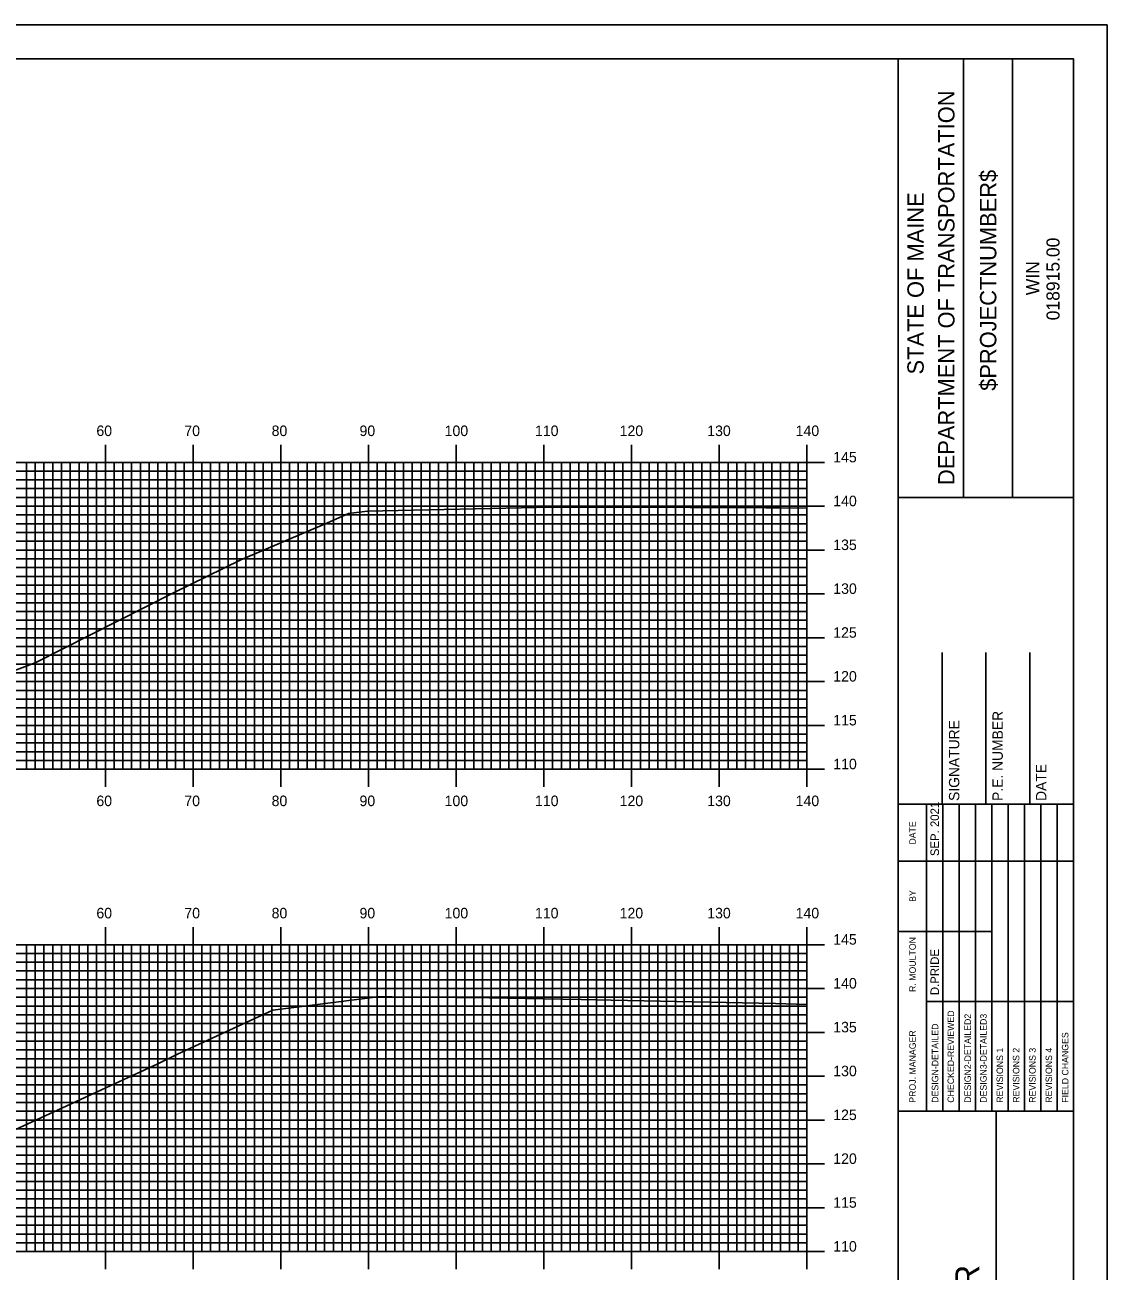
# Model space of a CAD drawing. Extents: x 853328 to 853671, y 364661 to 364881.
# Drawn here: x 853544.1 to 853667.5, y 364739.1 to 364881.3 of the extents above; entities that cross this region are included whole.
import ezdxf

# ---------------------------------------------------------------- set-up
doc = ezdxf.new("R2010")
doc.units = 0
for name, color, linetype in [('BORDER', 7, 'Continuous'), ('H_V ANNOTATION', 7, 'Continuous'), ('MAJOR', 7, 'Continuous'), ('MINOR', 7, 'Continuous'), ('PLOT BOUNDARY', 7, 'Continuous'), ('S_Roadway_Centerline', 7, 'Continuous')]:
    doc.layers.add(name, color=color, linetype=linetype)

msp = doc.modelspace()

# ---------------------------------------------------------------- linework, layer by layer
at = {"layer": 'BORDER'}
for p, q in [((853643.69, 364667.37), (853643.69, 364877.37)), ((853651.15, 364827.36), (853651.15, 364877.36)), ((853656.74, 364827.36), (853656.74, 364877.36)), ((853643.7, 364827.36), (853663.69, 364827.36)), ((853648.69, 364792.38), (853648.69, 364809.67)), ((853653.69, 364792.38), (853653.69, 364809.67)), ((853658.69, 364792.38), (853658.69, 364809.67)), ((853643.69, 364792.38), (853663.69, 364792.38)), ((853643.69, 364757.38), (853663.69, 364757.38)), ((853654.88, 364687.38), (853654.88, 364757.38))]:
    msp.add_line(p, q, dxfattribs=at)
msp.add_lwpolyline([(853343.69, 364667.37), (853663.69, 364667.37), (853663.69, 364877.37), (853343.69, 364877.37)], close=True, dxfattribs=at)
for points in [[(853646.92, 364785.88), (853646.92, 364792.38)], [(853648.79, 364757.38), (853648.79, 364792.38)], [(853650.65, 364792.38), (853650.65, 364757.38)], [(853652.52, 364757.38), (853652.52, 364792.38)], [(853654.38, 364757.38), (853654.38, 364792.38)], [(853656.24, 364757.38), (853656.24, 364792.38)], [(853658.11, 364757.38), (853658.11, 364792.38)], [(853659.97, 364757.38), (853659.97, 364792.38)], [(853661.83, 364757.38), (853661.83, 364792.38)], [(853646.93, 364757.38), (853646.93, 364790.96)], [(853643.69, 364785.88), (853663.69, 364785.88)], [(853643.69, 364777.88), (853646.93, 364777.88)], [(853646.92, 364777.88), (853654.38, 364777.88)], [(853646.92, 364769.88), (853663.69, 364769.88)]]:
    msp.add_lwpolyline(points, dxfattribs=at)
at = {"layer": 'MAJOR'}
for p, q in [((853553.29, 364833.38), (853553.29, 364831.37)), ((853563.29, 364833.38), (853563.29, 364831.37)), ((853573.29, 364833.38), (853573.29, 364831.37)), ((853583.29, 364833.38), (853583.29, 364831.37)), ((853593.29, 364833.38), (853593.29, 364831.37)), ((853603.29, 364833.38), (853603.29, 364831.37)), ((853613.29, 364833.38), (853613.29, 364831.37)), ((853623.29, 364833.38), (853623.29, 364831.37)), ((853633.29, 364833.38), (853633.29, 364831.37)), ((853353.29, 364831.37), (853633.29, 364831.37)), ((853353.29, 364831.37), (853633.29, 364831.37)), ((853553.29, 364796.37), (853553.29, 364831.37)), ((853563.29, 364796.37), (853563.29, 364831.37)), ((853573.29, 364796.37), (853573.29, 364831.37)), ((853583.29, 364796.37), (853583.29, 364831.37)), ((853593.29, 364796.37), (853593.29, 364831.37)), ((853603.29, 364796.37), (853603.29, 364831.37)), ((853613.29, 364796.37), (853613.29, 364831.37)), ((853623.29, 364796.37), (853623.29, 364831.37)), ((853635.3, 364831.37), (853631.29, 364831.37)), ((853633.29, 364796.37), (853633.29, 364831.37)), ((853633.29, 364796.37), (853633.29, 364831.37)), ((853353.29, 364826.37), (853633.29, 364826.37)), ((853635.3, 364826.37), (853631.29, 364826.37)), ((853353.29, 364821.37), (853633.29, 364821.37)), ((853635.3, 364821.37), (853631.29, 364821.37)), ((853353.29, 364816.37), (853633.29, 364816.37)), ((853635.3, 364816.37), (853631.29, 364816.37)), ((853353.29, 364811.37), (853633.29, 364811.37)), ((853635.3, 364811.37), (853631.29, 364811.37)), ((853353.29, 364806.37), (853633.29, 364806.37)), ((853635.3, 364806.37), (853631.29, 364806.37)), ((853353.29, 364801.37), (853633.29, 364801.37)), ((853635.3, 364801.37), (853631.29, 364801.37)), ((853353.29, 364796.37), (853633.29, 364796.37)), ((853353.29, 364796.37), (853633.29, 364796.37)), ((853553.29, 364794.37), (853553.29, 364796.37)), ((853563.29, 364794.37), (853563.29, 364796.37)), ((853573.29, 364794.37), (853573.29, 364796.37)), ((853583.29, 364794.37), (853583.29, 364796.37)), ((853593.29, 364794.37), (853593.29, 364796.37)), ((853603.29, 364794.37), (853603.29, 364796.37)), ((853613.29, 364794.37), (853613.29, 364796.37)), ((853623.29, 364794.37), (853623.29, 364796.37)), ((853635.3, 364796.37), (853631.29, 364796.37)), ((853633.29, 364794.37), (853633.29, 364796.37)), ((853553.29, 364778.38), (853553.29, 364776.37)), ((853563.29, 364778.38), (853563.29, 364776.37)), ((853573.29, 364778.38), (853573.29, 364776.37)), ((853583.29, 364778.38), (853583.29, 364776.37)), ((853593.29, 364778.38), (853593.29, 364776.37)), ((853603.29, 364778.38), (853603.29, 364776.37)), ((853613.29, 364778.38), (853613.29, 364776.37)), ((853623.29, 364778.38), (853623.29, 364776.37)), ((853633.29, 364778.38), (853633.29, 364776.37)), ((853353.29, 364776.37), (853633.29, 364776.37)), ((853353.29, 364776.37), (853633.29, 364776.37)), ((853553.29, 364741.37), (853553.29, 364776.37)), ((853563.29, 364741.37), (853563.29, 364776.37)), ((853573.29, 364741.37), (853573.29, 364776.37)), ((853583.29, 364741.37), (853583.29, 364776.37)), ((853593.29, 364741.37), (853593.29, 364776.37)), ((853603.29, 364741.37), (853603.29, 364776.37)), ((853613.29, 364741.37), (853613.29, 364776.37)), ((853623.29, 364741.37), (853623.29, 364776.37)), ((853635.3, 364776.37), (853631.29, 364776.37)), ((853633.29, 364741.37), (853633.29, 364776.37)), ((853633.29, 364741.37), (853633.29, 364776.37)), ((853353.29, 364771.37), (853633.29, 364771.37)), ((853635.3, 364771.37), (853631.29, 364771.37)), ((853353.29, 364766.37), (853633.29, 364766.37)), ((853635.3, 364766.37), (853631.29, 364766.37)), ((853353.29, 364761.37), (853633.29, 364761.37)), ((853635.3, 364761.37), (853631.29, 364761.37)), ((853353.29, 364756.37), (853633.29, 364756.37)), ((853635.3, 364756.37), (853631.29, 364756.37)), ((853353.29, 364751.37), (853633.29, 364751.37)), ((853635.3, 364751.37), (853631.29, 364751.37)), ((853353.29, 364746.37), (853633.29, 364746.37)), ((853635.3, 364746.37), (853631.29, 364746.37)), ((853353.29, 364741.37), (853633.29, 364741.37)), ((853353.29, 364741.37), (853633.29, 364741.37)), ((853553.29, 364739.37), (853553.29, 364741.37)), ((853563.29, 364739.37), (853563.29, 364741.37)), ((853573.29, 364739.37), (853573.29, 364741.37)), ((853583.29, 364739.37), (853583.29, 364741.37)), ((853593.29, 364739.37), (853593.29, 364741.37)), ((853603.29, 364739.37), (853603.29, 364741.37)), ((853613.29, 364739.37), (853613.29, 364741.37)), ((853623.29, 364739.37), (853623.29, 364741.37)), ((853635.3, 364741.37), (853631.29, 364741.37)), ((853633.29, 364739.37), (853633.29, 364741.37))]:
    msp.add_line(p, q, dxfattribs=at)
at = {"layer": 'MINOR'}
for p, q in [((853544.29, 364796.37), (853544.29, 364831.37)), ((853545.29, 364796.37), (853545.29, 364831.37)), ((853546.29, 364796.37), (853546.29, 364831.37)), ((853547.29, 364796.37), (853547.29, 364831.37)), ((853548.29, 364796.37), (853548.29, 364831.37)), ((853549.29, 364796.37), (853549.29, 364831.37)), ((853550.29, 364796.37), (853550.29, 364831.37)), ((853551.29, 364796.37), (853551.29, 364831.37)), ((853552.29, 364796.37), (853552.29, 364831.37)), ((853554.29, 364796.37), (853554.29, 364831.37)), ((853555.29, 364796.37), (853555.29, 364831.37)), ((853556.29, 364796.37), (853556.29, 364831.37)), ((853557.29, 364796.37), (853557.29, 364831.37)), ((853558.29, 364796.37), (853558.29, 364831.37)), ((853559.29, 364796.37), (853559.29, 364831.37)), ((853560.29, 364796.37), (853560.29, 364831.37)), ((853561.29, 364796.37), (853561.29, 364831.37)), ((853562.29, 364796.37), (853562.29, 364831.37)), ((853564.29, 364796.37), (853564.29, 364831.37)), ((853565.29, 364796.37), (853565.29, 364831.37)), ((853566.29, 364796.37), (853566.29, 364831.37)), ((853567.29, 364796.37), (853567.29, 364831.37)), ((853568.29, 364796.37), (853568.29, 364831.37)), ((853569.29, 364796.37), (853569.29, 364831.37)), ((853570.29, 364796.37), (853570.29, 364831.37)), ((853571.29, 364796.37), (853571.29, 364831.37)), ((853572.29, 364796.37), (853572.29, 364831.37)), ((853574.29, 364796.37), (853574.29, 364831.37)), ((853575.29, 364796.37), (853575.29, 364831.37)), ((853576.29, 364796.37), (853576.29, 364831.37)), ((853577.29, 364796.37), (853577.29, 364831.37)), ((853578.29, 364796.37), (853578.29, 364831.37)), ((853579.29, 364796.37), (853579.29, 364831.37)), ((853580.29, 364796.37), (853580.29, 364831.37)), ((853581.29, 364796.37), (853581.29, 364831.37)), ((853582.29, 364796.37), (853582.29, 364831.37)), ((853584.29, 364796.37), (853584.29, 364831.37)), ((853585.29, 364796.37), (853585.29, 364831.37)), ((853586.29, 364796.37), (853586.29, 364831.37)), ((853587.29, 364796.37), (853587.29, 364831.37)), ((853588.29, 364796.37), (853588.29, 364831.37)), ((853589.29, 364796.37), (853589.29, 364831.37)), ((853590.29, 364796.37), (853590.29, 364831.37)), ((853591.29, 364796.37), (853591.29, 364831.37)), ((853592.29, 364796.37), (853592.29, 364831.37)), ((853594.29, 364796.37), (853594.29, 364831.37)), ((853595.29, 364796.37), (853595.29, 364831.37)), ((853596.29, 364796.37), (853596.29, 364831.37)), ((853597.29, 364796.37), (853597.29, 364831.37)), ((853598.29, 364796.37), (853598.29, 364831.37)), ((853599.29, 364796.37), (853599.29, 364831.37)), ((853600.29, 364796.37), (853600.29, 364831.37)), ((853601.29, 364796.37), (853601.29, 364831.37)), ((853602.29, 364796.37), (853602.29, 364831.37)), ((853604.29, 364796.37), (853604.29, 364831.37)), ((853605.29, 364796.37), (853605.29, 364831.37)), ((853606.29, 364796.37), (853606.29, 364831.37)), ((853607.29, 364796.37), (853607.29, 364831.37)), ((853608.29, 364796.37), (853608.29, 364831.37)), ((853609.29, 364796.37), (853609.29, 364831.37)), ((853610.29, 364796.37), (853610.29, 364831.37)), ((853611.29, 364796.37), (853611.29, 364831.37)), ((853612.29, 364796.37), (853612.29, 364831.37)), ((853614.29, 364796.37), (853614.29, 364831.37)), ((853615.29, 364796.37), (853615.29, 364831.37)), ((853616.29, 364796.37), (853616.29, 364831.37)), ((853617.29, 364796.37), (853617.29, 364831.37)), ((853618.29, 364796.37), (853618.29, 364831.37)), ((853619.29, 364796.37), (853619.29, 364831.37)), ((853620.29, 364796.37), (853620.29, 364831.37)), ((853621.29, 364796.37), (853621.29, 364831.37)), ((853622.29, 364796.37), (853622.29, 364831.37)), ((853624.29, 364796.37), (853624.29, 364831.37)), ((853625.29, 364796.37), (853625.29, 364831.37)), ((853626.29, 364796.37), (853626.29, 364831.37)), ((853627.29, 364796.37), (853627.29, 364831.37)), ((853628.29, 364796.37), (853628.29, 364831.37)), ((853629.29, 364796.37), (853629.29, 364831.37)), ((853630.29, 364796.37), (853630.29, 364831.37)), ((853631.29, 364796.37), (853631.29, 364831.37)), ((853632.29, 364796.37), (853632.29, 364831.37)), ((853353.29, 364830.37), (853633.29, 364830.37)), ((853633.29, 364830.37), (853631.29, 364830.37)), ((853353.29, 364829.37), (853633.29, 364829.37)), ((853353.29, 364828.37), (853633.29, 364828.37)), ((853633.29, 364829.37), (853631.29, 364829.37)), ((853633.29, 364828.37), (853631.29, 364828.37)), ((853353.29, 364827.37), (853633.29, 364827.37)), ((853633.29, 364827.37), (853631.29, 364827.37)), ((853353.29, 364825.37), (853633.29, 364825.37)), ((853353.29, 364824.37), (853633.29, 364824.37)), ((853633.29, 364825.37), (853631.29, 364825.37)), ((853633.29, 364824.37), (853631.29, 364824.37)), ((853353.29, 364823.37), (853633.29, 364823.37)), ((853633.29, 364823.37), (853631.29, 364823.37)), ((853353.29, 364822.37), (853633.29, 364822.37)), ((853633.29, 364822.37), (853631.29, 364822.37)), ((853353.29, 364820.37), (853633.29, 364820.37)), ((853633.29, 364820.37), (853631.29, 364820.37)), ((853353.29, 364819.37), (853633.29, 364819.37)), ((853633.29, 364819.37), (853631.29, 364819.37)), ((853353.29, 364818.37), (853633.29, 364818.37)), ((853353.29, 364817.37), (853633.29, 364817.37)), ((853633.29, 364818.37), (853631.29, 364818.37)), ((853633.29, 364817.37), (853631.29, 364817.37)), ((853353.29, 364815.37), (853633.29, 364815.37)), ((853353.29, 364814.37), (853633.29, 364814.37)), ((853633.29, 364815.37), (853631.29, 364815.37)), ((853633.29, 364814.37), (853631.29, 364814.37)), ((853353.29, 364813.37), (853633.29, 364813.37)), ((853633.29, 364813.37), (853631.29, 364813.37)), ((853353.29, 364812.37), (853633.29, 364812.37)), ((853633.29, 364812.37), (853631.29, 364812.37)), ((853353.29, 364810.37), (853633.29, 364810.37)), ((853633.29, 364810.37), (853631.29, 364810.37)), ((853353.29, 364809.37), (853633.29, 364809.37)), ((853633.29, 364809.37), (853631.29, 364809.37)), ((853353.29, 364808.37), (853633.29, 364808.37)), ((853353.29, 364807.37), (853633.29, 364807.37)), ((853633.29, 364808.37), (853631.29, 364808.37)), ((853633.29, 364807.37), (853631.29, 364807.37)), ((853353.29, 364805.37), (853633.29, 364805.37)), ((853353.29, 364804.37), (853633.29, 364804.37)), ((853633.29, 364805.37), (853631.29, 364805.37)), ((853633.29, 364804.37), (853631.29, 364804.37)), ((853353.29, 364803.37), (853633.29, 364803.37)), ((853633.29, 364803.37), (853631.29, 364803.37)), ((853353.29, 364802.37), (853633.29, 364802.37)), ((853633.29, 364802.37), (853631.29, 364802.37)), ((853353.29, 364800.37), (853633.29, 364800.37)), ((853633.29, 364800.37), (853631.29, 364800.37)), ((853353.29, 364799.37), (853633.29, 364799.37)), ((853633.29, 364799.37), (853631.29, 364799.37)), ((853353.29, 364798.37), (853633.29, 364798.37)), ((853353.29, 364797.37), (853633.29, 364797.37)), ((853633.29, 364798.37), (853631.29, 364798.37)), ((853633.29, 364797.37), (853631.29, 364797.37)), ((853544.29, 364741.37), (853544.29, 364776.37)), ((853545.29, 364741.37), (853545.29, 364776.37)), ((853546.29, 364741.37), (853546.29, 364776.37)), ((853547.29, 364741.37), (853547.29, 364776.37)), ((853548.29, 364741.37), (853548.29, 364776.37)), ((853549.29, 364741.37), (853549.29, 364776.37)), ((853550.29, 364741.37), (853550.29, 364776.37)), ((853551.29, 364741.37), (853551.29, 364776.37)), ((853552.29, 364741.37), (853552.29, 364776.37)), ((853554.29, 364741.37), (853554.29, 364776.37)), ((853555.29, 364741.37), (853555.29, 364776.37)), ((853556.29, 364741.37), (853556.29, 364776.37)), ((853557.29, 364741.37), (853557.29, 364776.37)), ((853558.29, 364741.37), (853558.29, 364776.37)), ((853559.29, 364741.37), (853559.29, 364776.37)), ((853560.29, 364741.37), (853560.29, 364776.37)), ((853561.29, 364741.37), (853561.29, 364776.37)), ((853562.29, 364741.37), (853562.29, 364776.37)), ((853564.29, 364741.37), (853564.29, 364776.37)), ((853565.29, 364741.37), (853565.29, 364776.37)), ((853566.29, 364741.37), (853566.29, 364776.37)), ((853567.29, 364741.37), (853567.29, 364776.37)), ((853568.29, 364741.37), (853568.29, 364776.37)), ((853569.29, 364741.37), (853569.29, 364776.37)), ((853570.29, 364741.37), (853570.29, 364776.37)), ((853571.29, 364741.37), (853571.29, 364776.37)), ((853572.29, 364741.37), (853572.29, 364776.37)), ((853574.29, 364741.37), (853574.29, 364776.37)), ((853575.29, 364741.37), (853575.29, 364776.37)), ((853576.29, 364741.37), (853576.29, 364776.37)), ((853577.29, 364741.37), (853577.29, 364776.37)), ((853578.29, 364741.37), (853578.29, 364776.37)), ((853579.29, 364741.37), (853579.29, 364776.37)), ((853580.29, 364741.37), (853580.29, 364776.37)), ((853581.29, 364741.37), (853581.29, 364776.37)), ((853582.29, 364741.37), (853582.29, 364776.37)), ((853584.29, 364741.37), (853584.29, 364776.37)), ((853585.29, 364741.37), (853585.29, 364776.37)), ((853586.29, 364741.37), (853586.29, 364776.37)), ((853587.29, 364741.37), (853587.29, 364776.37)), ((853588.29, 364741.37), (853588.29, 364776.37)), ((853589.29, 364741.37), (853589.29, 364776.37)), ((853590.29, 364741.37), (853590.29, 364776.37)), ((853591.29, 364741.37), (853591.29, 364776.37)), ((853592.29, 364741.37), (853592.29, 364776.37)), ((853594.29, 364741.37), (853594.29, 364776.37)), ((853595.29, 364741.37), (853595.29, 364776.37)), ((853596.29, 364741.37), (853596.29, 364776.37)), ((853597.29, 364741.37), (853597.29, 364776.37)), ((853598.29, 364741.37), (853598.29, 364776.37)), ((853599.29, 364741.37), (853599.29, 364776.37)), ((853600.29, 364741.37), (853600.29, 364776.37)), ((853601.29, 364741.37), (853601.29, 364776.37)), ((853602.29, 364741.37), (853602.29, 364776.37)), ((853604.29, 364741.37), (853604.29, 364776.37)), ((853605.29, 364741.37), (853605.29, 364776.37)), ((853606.29, 364741.37), (853606.29, 364776.37)), ((853607.29, 364741.37), (853607.29, 364776.37)), ((853608.29, 364741.37), (853608.29, 364776.37)), ((853609.29, 364741.37), (853609.29, 364776.37)), ((853610.29, 364741.37), (853610.29, 364776.37)), ((853611.29, 364741.37), (853611.29, 364776.37)), ((853612.29, 364741.37), (853612.29, 364776.37)), ((853614.29, 364741.37), (853614.29, 364776.37)), ((853615.29, 364741.37), (853615.29, 364776.37)), ((853616.29, 364741.37), (853616.29, 364776.37)), ((853617.29, 364741.37), (853617.29, 364776.37)), ((853618.29, 364741.37), (853618.29, 364776.37)), ((853619.29, 364741.37), (853619.29, 364776.37)), ((853620.29, 364741.37), (853620.29, 364776.37)), ((853621.29, 364741.37), (853621.29, 364776.37)), ((853622.29, 364741.37), (853622.29, 364776.37)), ((853624.29, 364741.37), (853624.29, 364776.37)), ((853625.29, 364741.37), (853625.29, 364776.37)), ((853626.29, 364741.37), (853626.29, 364776.37)), ((853627.29, 364741.37), (853627.29, 364776.37)), ((853628.29, 364741.37), (853628.29, 364776.37)), ((853629.29, 364741.37), (853629.29, 364776.37)), ((853630.29, 364741.37), (853630.29, 364776.37)), ((853631.29, 364741.37), (853631.29, 364776.37)), ((853632.29, 364741.37), (853632.29, 364776.37)), ((853353.29, 364775.37), (853633.29, 364775.37)), ((853353.29, 364774.37), (853633.29, 364774.37)), ((853633.29, 364775.37), (853631.29, 364775.37)), ((853633.29, 364774.37), (853631.29, 364774.37)), ((853353.29, 364773.37), (853633.29, 364773.37)), ((853633.29, 364773.37), (853631.29, 364773.37)), ((853353.29, 364772.37), (853633.29, 364772.37)), ((853633.29, 364772.37), (853631.29, 364772.37)), ((853353.29, 364770.37), (853633.29, 364770.37)), ((853633.29, 364770.37), (853631.29, 364770.37)), ((853353.29, 364769.37), (853633.29, 364769.37)), ((853633.29, 364769.37), (853631.29, 364769.37)), ((853353.29, 364768.37), (853633.29, 364768.37)), ((853353.29, 364767.37), (853633.29, 364767.37)), ((853633.29, 364768.37), (853631.29, 364768.37)), ((853633.29, 364767.37), (853631.29, 364767.37)), ((853353.29, 364765.37), (853633.29, 364765.37)), ((853633.29, 364765.37), (853631.29, 364765.37)), ((853353.29, 364764.37), (853633.29, 364764.37)), ((853353.29, 364763.37), (853633.29, 364763.37)), ((853633.29, 364764.37), (853631.29, 364764.37)), ((853633.29, 364763.37), (853631.29, 364763.37)), ((853353.29, 364762.37), (853633.29, 364762.37)), ((853633.29, 364762.37), (853631.29, 364762.37)), ((853353.29, 364760.37), (853633.29, 364760.37)), ((853633.29, 364760.37), (853631.29, 364760.37)), ((853353.29, 364759.37), (853633.29, 364759.37)), ((853633.29, 364759.37), (853631.29, 364759.37)), ((853353.29, 364758.37), (853633.29, 364758.37)), ((853353.29, 364757.37), (853633.29, 364757.37)), ((853633.29, 364758.37), (853631.29, 364758.37)), ((853633.29, 364757.37), (853631.29, 364757.37)), ((853353.29, 364755.37), (853633.29, 364755.37)), ((853633.29, 364755.37), (853631.29, 364755.37)), ((853353.29, 364754.37), (853633.29, 364754.37)), ((853353.29, 364753.37), (853633.29, 364753.37)), ((853633.29, 364754.37), (853631.29, 364754.37)), ((853633.29, 364753.37), (853631.29, 364753.37)), ((853353.29, 364752.37), (853633.29, 364752.37)), ((853633.29, 364752.37), (853631.29, 364752.37)), ((853353.29, 364750.37), (853633.29, 364750.37)), ((853633.29, 364750.37), (853631.29, 364750.37)), ((853353.29, 364749.37), (853633.29, 364749.37)), ((853633.29, 364749.37), (853631.29, 364749.37)), ((853353.29, 364748.37), (853633.29, 364748.37)), ((853353.29, 364747.37), (853633.29, 364747.37)), ((853633.29, 364748.37), (853631.29, 364748.37)), ((853633.29, 364747.37), (853631.29, 364747.37)), ((853353.29, 364745.37), (853633.29, 364745.37)), ((853633.29, 364745.37), (853631.29, 364745.37)), ((853353.29, 364744.37), (853633.29, 364744.37)), ((853353.29, 364743.37), (853633.29, 364743.37)), ((853633.29, 364744.37), (853631.29, 364744.37)), ((853633.29, 364743.37), (853631.29, 364743.37)), ((853353.29, 364742.37), (853633.29, 364742.37)), ((853633.29, 364742.37), (853631.29, 364742.37))]:
    msp.add_line(p, q, dxfattribs=at)
at = {"layer": 'PLOT BOUNDARY'}
msp.add_lwpolyline([(853327.51, 364661.25), (853667.51, 364661.25), (853667.51, 364881.25), (853327.51, 364881.25)], close=True, dxfattribs=at)
at = {"layer": 'S_Roadway_Centerline'}
for points in [[(853539.28, 364806.27), (853545.28, 364808.52), (853561.07, 364816.51), (853568.75, 364820.24), (853578.56, 364824.44), (853581.03, 364825.54), (853583.18, 364825.79), (853604.21, 364826.26), (853604.82, 364826.26), (853605.4, 364826.27), (853611.36, 364826.25), (853628.61, 364826.19), (853630.34, 364826.17), (853633.29, 364826.14)], [(853539.98, 364753.87), (853559.29, 364762.8), (853561.53, 364763.88), (853572.4, 364768.92), (853584.36, 364770.44), (853585.99, 364770.43), (853597.04, 364770.3), (853607.54, 364770.13), (853610.95, 364770.05), (853629.72, 364769.67), (853633.29, 364769.56)]]:
    msp.add_lwpolyline(points, dxfattribs=at)

# ---------------------------------------------------------------- texts
at = {"layer": 'BORDER'}
for s, height, p in [('DEPARTMENT OF TRANSPORTATION', 1.8635, (853650.11, 364828.78)), ('$PROJECTNUMBER$', 1.8635, (853654.88, 364839.53)), ('STATE OF MAINE', 1.8635, (853646.6, 364841.39)), ('018915.00', 1.491, (853662.09, 364847.57)), ('WIN', 1.491, (853659.77, 364850.43)), ('P.E. NUMBER', 1.1811, (853655.62, 364792.76)), ('SIGNATURE', 1.181, (853650.66, 364792.76)), ('DATE', 1.181, (853660.58, 364792.76)), ('SEP. 2021', 0.969, (853648.34, 364786.47)), ('DATE', 0.743, (853645.7, 364787.79)), ('BY', 0.743, (853645.7, 364781.25)), ('R. MOULTON', 0.745, (853645.7, 364770.98)), ('D.PRIDE', 0.969, (853648.34, 364770.62)), ('CHECKED-REVIEWED', 0.7455, (853650.06, 364758.35)), ('DESIGN-DETAILED', 0.7455, (853648.27, 364758.35)), ('DESIGN2-DETAILED2', 0.7455, (853651.99, 364758.35)), ('DESIGN3-DETAILED3', 0.7455, (853653.78, 364758.35)), ('PROJ. MANAGER', 0.7455, (853645.7, 364758.35)), ('FIELD CHANGES', 0.7455, (853663.1, 364758.35)), ('REVISIONS 1', 0.7455, (853655.65, 364758.35)), ('REVISIONS 2', 0.7455, (853657.51, 364758.35)), ('REVISIONS 3', 0.7455, (853659.37, 364758.35)), ('REVISIONS 4', 0.7455, (853661.24, 364758.35)), ('I-395/ROUTE 9 CONNECTOR', 2.7557, (853652.96, 364689.7))]:
    msp.add_text(s, height=height, rotation=90, dxfattribs=at).set_placement(p)
at = {"layer": 'H_V ANNOTATION'}
for s, p in [('60', (853552.27, 364834.37)), ('70', (853562.3, 364834.37)), ('80', (853572.25, 364834.37)), ('90', (853582.27, 364834.37)), ('100', (853591.98, 364834.37)), ('110', (853602.28, 364834.37)), ('120', (853611.93, 364834.37)), ('130', (853621.92, 364834.37)), ('140', (853632, 364834.37)), ('145', (853636.29, 364831.37)), ('140', (853636.29, 364826.37)), ('135', (853636.29, 364821.37)), ('130', (853636.29, 364816.37)), ('125', (853636.29, 364811.37)), ('120', (853636.29, 364806.37)), ('115', (853636.29, 364801.37)), ('110', (853636.29, 364796.37)), ('60', (853552.27, 364792.17)), ('70', (853562.3, 364792.17)), ('80', (853572.25, 364792.17)), ('90', (853582.27, 364792.17)), ('100', (853591.98, 364792.17)), ('110', (853602.28, 364792.17)), ('120', (853611.93, 364792.17)), ('130', (853621.92, 364792.17)), ('140', (853632, 364792.17)), ('60', (853552.27, 364779.37)), ('70', (853562.3, 364779.37)), ('80', (853572.25, 364779.37)), ('90', (853582.27, 364779.37)), ('100', (853591.98, 364779.37)), ('110', (853602.28, 364779.37)), ('120', (853611.93, 364779.37)), ('130', (853621.92, 364779.37)), ('140', (853632, 364779.37)), ('145', (853636.29, 364776.37)), ('140', (853636.29, 364771.37)), ('135', (853636.29, 364766.37)), ('130', (853636.29, 364761.37)), ('125', (853636.29, 364756.37)), ('120', (853636.29, 364751.37)), ('115', (853636.29, 364746.37)), ('110', (853636.29, 364741.37))]:
    msp.add_text(s, height=1.2, dxfattribs=at).set_placement(p)

doc.saveas('drawing.dxf')
